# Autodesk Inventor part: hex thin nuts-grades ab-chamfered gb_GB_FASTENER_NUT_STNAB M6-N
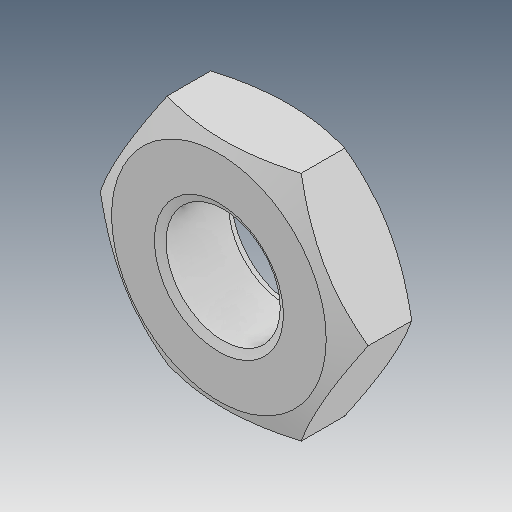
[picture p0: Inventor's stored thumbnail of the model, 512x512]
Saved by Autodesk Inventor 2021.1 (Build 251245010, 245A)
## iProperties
Created: 2019-04
Part Number: hex thin nuts-grades ab-chamfered gb_GB_FASTENER_NUT_STNAB M6-N
Material: Ogólny
Document SubType Name: Modeling
Designer: user
Density: 1 g/cm^3
Appearance: Domyślna
Author: user
Revision Number: ÈÎºÎ
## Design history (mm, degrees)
feature "ÊäÈë1"
node "Bryła1"
